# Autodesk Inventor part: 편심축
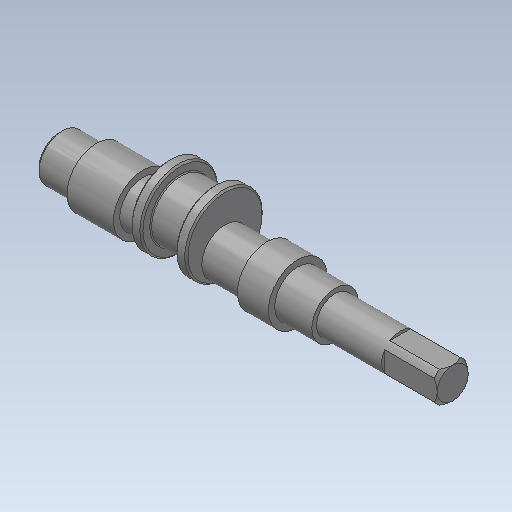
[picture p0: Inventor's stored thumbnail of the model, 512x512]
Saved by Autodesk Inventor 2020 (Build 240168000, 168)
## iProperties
Created: 2015-12
Part Number: 편심축
Document SubType Name: Modeling
Designer: mdu
Density: 7.86 g/cm^3
Mass: 201.985 g
Surface Area: 79.4631 cm^2
Volume: 25.6978 cm^3
Material: 강철, 연강
Appearance: 강철
Company: 한국ATC센터
Author: mdu
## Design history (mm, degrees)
sketch "스케치1"
  geometry: L1 (-63.5, 0)-(63.5, 0); L2 (-63.5, 0)-(-63.5, 7.5); L3 (-63.5, 7.5)-(-51.5, 7.5); L4 (-51.5, 7.5)-(-51.5, 9.5); L5 (-51.5, 9.5)-(-36.5, 9.5); L6 (-36.5, 9.5)-(-36.5, 7.5); L7 (-36.5, 7.5)-(25.5, 7.5); L8 (63.5, 6)-(63.5, 0); L9 (13.5, 7.5)-(13.5, 9.5); L10 (13.5, 9.5)-(3.5, 9.5); L11 (3.5, 9.5)-(3.5, 7.5); L12 (25.5, 7.5)-(25.5, 6); L13 (25.5, 6)-(63.5, 6); 2 further points
  constraints: 26 end point, 6 perpendicular, 5 parallel, 2 collinear, 2 point on line, 1 coincident, 1 horizontal, 1 midpoint
  dimensions: "d2" = 15 diameter of L7 L1; "d4" = 15 distance of L4.end L5.end; "d5" = 19 diameter of L5 L1; "d24" = 10 distance of L9.end L10.end; "d25" = 19 diameter of L10 L1; "d27" = 40 distance between parallel lines of L11 L6; "d28" = 12 distance of L2.end L3.end; "d29" = 50 distance between parallel lines of L8 L9; "d41" = 38 distance between parallel lines of L8 L12; "d42" = 12 diameter of L13 L1
revolve "회전1" stored, may be unused: angle "d6" = 90 deg
node "작업 평면1"
sketch "스케치2"
  geometry: C1 r 7.5 at (0, 0) reference; C2 r 12.5 at (0, 4.5); 1 further point
  constraints: 1 centre point, 1 vertical alignment
  dimensions: "d8" = 4.5 distance of point (0, 0) C2.centre; "d9" = 25 diameter of C2
extrude "돌출1" join sketch "스케치2" distance "d10" = 18; taper "d11" = 0 deg
chamfer "모따기1" distance "d12" = 1; stored, may be unused: second distance "d13" = 2, angle "d14" = 45 deg
chamfer "모따기2" distance "d15" = 0.5; stored, may be unused: second distance "d16" = 2, angle "d17" = 45 deg
node "작업 평면2"
revolve "회전2" stored, may be unused: angle "d26" = 90 deg
node "작업 평면3"
sketch "스케치10"
  geometry: L1 (-5, -5)-(5, -5); L2 (5, -5)-(5, 5); L3 (5, 5)-(-5, 5); L4 (-5, 5)-(-5, -5); L5 (-5, -5)-(5, 5); L6 (5, -5)-(-5, 5); C1 r 5 at (0, 0) reference; C2 r 6 at (0, 0) reference; A1 r 6 centre (0, 0) between (5, 3.317) and (3.317, 5); A2 r 6 centre (0, 0) between (5, -3.317) and (5, 3.317); A3 r 6 centre (0, 0) between (3.317, -5) and (5, -3.317); A4 r 6 centre (0, 0) between (-3.317, -5) and (3.317, -5); A5 r 6 centre (0, 0) between (-5, -3.317) and (-3.317, -5); A6 r 6 centre (0, 0) between (-5, 3.317) and (-5, -3.317); A7 r 6 centre (0, 0) between (-3.317, 5) and (-5, 3.317); A8 r 6 centre (0, 0) between (3.317, 5) and (-3.317, 5)
  constraints: 16 point on circle, 12 end point, 8 centre point, 8 point on line, 2 midpoint, 2 parallel, 2 tangent, 1 coincident, 1 concentric, 1 horizontal, 1 perpendicular
extrude "돌출4" cut sketch "스케치10" distance "d55" = 17; taper "d56" = 0 deg
node "작업 평면5"
sketch "스케치11"
  geometry: C1 r 12.5 at (0, 0) reference; C2 r 9.5 at (0, 0); 1 further point
  constraints: 1 centre point
  dimensions: "d57" = 3 radial gap between concentric circles of C1 C2
extrude "돌출5" cut sketch "스케치11" stored distance "d58" = 11; taper "d59" = 0 deg
fillet "모깎기1" dims "d60" = 0.3
chamfer "모따기4" distance "d61" = 0.5; stored, may be unused: second distance "d62" = 2, angle "d63" = 45 deg
node "솔리드1"
node "절단 모서리 투영2"
other parameters: "d7" = 8.5
